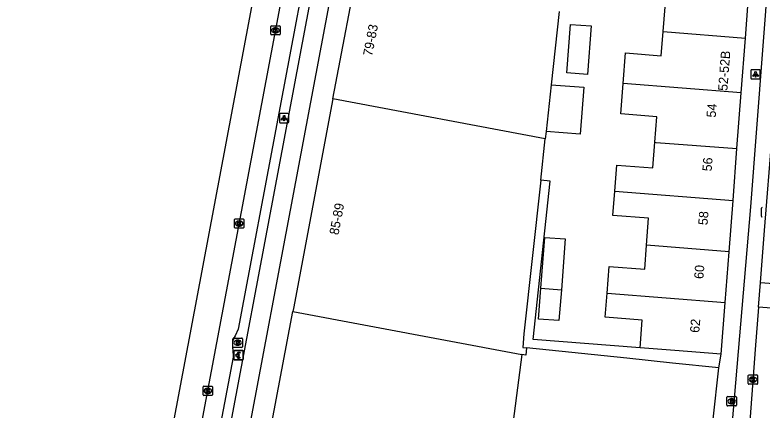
# Model space of a CAD drawing. Extents: x 161845 to 162341, y 381620 to 382158.
# Drawn here: x 161857.3 to 161937.3, y 381807.6 to 381850 of the extents above; entities that cross this region are included whole.
import ezdxf

# ---------------------------------------------------------------- set-up
doc = ezdxf.new("R2010")
doc.units = 0
for name, color, linetype in [('IMGEO_Betaalautomaat', 7, 'Continuous'), ('IMGEO_Brandkraan', 7, 'Continuous'), ('IMGEO_Fietspad_gesloten', 7, 'Continuous'), ('IMGEO_Kolk', 7, 'Continuous'), ('IMGEO_Lichtpunt', 7, 'Continuous'), ('IMGEO_OVBaan_gesloten', 7, 'Continuous'), ('IMGEO_Pand', 7, 'Continuous'), ('IMGEO_Pand_nummerreeks', 7, 'Continuous'), ('IMGEO_Parkeervlak_open', 7, 'Continuous'), ('IMGEO_Rijbaan_lokaal_gesloten', 7, 'Continuous'), ('IMGEO_Rijbaan_lokaal_open', 7, 'Continuous'), ('IMGEO_Voetpad_open', 7, 'Continuous')]:
    doc.layers.add(name, color=color, linetype=linetype)

msp = doc.modelspace()

# ---------------------------------------------------------------- linework, layer by layer
at = {"layer": 'IMGEO_Betaalautomaat'}
for p, q in [((161880.759, 381813.075), (161880.759, 381813.916)), ((161880.759, 381813.916), (161880.759, 381813.075)), ((161880.834, 381813.999), (161881.675, 381813.999)), ((161881.675, 381813.999), (161880.834, 381813.999)), ((161881.042, 381813.463), (161881.042, 381813.531)), ((161881.163, 381813.531), (161881.163, 381813.463)), ((161881.421, 381813.804), (161881.404, 381813.704)), ((161881.758, 381813.925), (161881.758, 381813.084)), ((161881.758, 381813.084), (161881.758, 381813.925)), ((161881.684, 381813), (161880.843, 381813)), ((161880.843, 381813), (161881.684, 381813)), ((161881.408, 381813.298), (161881.43, 381813.211))]:
    msp.add_line(p, q, dxfattribs=at)
for points in [[(161881.042, 381813.531), (161880.973, 381813.531), (161880.973, 381813.6), (161881.052, 381813.6)], [(161881.174, 381813.6), (161881.321, 381813.6), (161881.321, 381813.531), (161881.163, 381813.531)], [(161881.047, 381813.394), (161880.973, 381813.394), (161880.973, 381813.463), (161881.042, 381813.463)], [(161881.163, 381813.463), (161881.321, 381813.463), (161881.321, 381813.394), (161881.177, 381813.394)]]:
    msp.add_lwpolyline(points, dxfattribs=at)
for centre, radius, start, end in [((161880.837, 381813.922), 0.0779, 92.4484, 184.28452), ((161880.837, 381813.922), 0.0779, 92.4484, 184.28452), ((161881.335, 381813.524), 0.293, 73.01398, 165.01395), ((161881.341, 381813.537), 0.179, 69.32359, 159.56827), ((161881.681, 381813.922), 0.0779, 2.4484, 94.28452), ((161881.681, 381813.922), 0.0779, 2.4484, 94.28452), ((161880.837, 381813.078), 0.0779, 182.4484, 274.28452), ((161880.837, 381813.078), 0.0779, 182.4484, 274.28452), ((161881.308, 381813.449), 0.267, 191.80956, 297.03891), ((161881.341, 381813.464), 0.179, 202.76249, 291.86925), ((161881.681, 381813.078), 0.0779, 272.4484, 4.28452), ((161881.681, 381813.078), 0.0779, 272.4484, 4.28452)]:
    msp.add_arc(centre, radius, start, end, dxfattribs=at)
at = {"layer": 'IMGEO_Brandkraan'}
for p, q in [((161880.66, 381814.422), (161880.66, 381815.274)), ((161880.735, 381815.348), (161881.587, 381815.348)), ((161881.148, 381815.128), (161881.173, 381815.128)), ((161881.661, 381815.274), (161881.661, 381814.422)), ((161881.587, 381814.348), (161880.735, 381814.348)), ((161881.171, 381814.568), (161881.146, 381814.568)), ((161933.545, 381808.144), (161933.545, 381808.996)), ((161933.62, 381809.07), (161934.472, 381809.07)), ((161934.033, 381808.85), (161934.058, 381808.85)), ((161934.546, 381808.996), (161934.546, 381808.144)), ((161934.472, 381808.07), (161933.62, 381808.07)), ((161934.056, 381808.29), (161934.031, 381808.29))]:
    msp.add_line(p, q, dxfattribs=at)
for points in [[(161880.66, 381814.422), (161880.66, 381815.274)], [(161880.735, 381815.348), (161881.587, 381815.348)], [(161881.661, 381815.274), (161881.661, 381814.422)], [(161881.587, 381814.348), (161880.735, 381814.348)], [(161881.008, 381815.048), (161881.008, 381814.648), (161881.221, 381814.648)], [(161881.239, 381815.048), (161881.008, 381815.048)], [(161881.187, 381814.967), (161881.133, 381814.967), (161881.133, 381814.891)], [(161881.133, 381814.891), (161881.186, 381814.891)], [(161881.195, 381814.815), (161881.133, 381814.815), (161881.133, 381814.734)], [(161881.133, 381814.734), (161881.195, 381814.734)], [(161933.545, 381808.144), (161933.545, 381808.996)], [(161933.62, 381809.07), (161934.472, 381809.07)], [(161933.893, 381808.77), (161933.893, 381808.37), (161934.106, 381808.37)], [(161934.124, 381808.77), (161933.893, 381808.77)], [(161934.546, 381808.996), (161934.546, 381808.144)], [(161934.472, 381808.07), (161933.62, 381808.07)], [(161934.072, 381808.689), (161934.018, 381808.689), (161934.018, 381808.613)], [(161934.018, 381808.613), (161934.071, 381808.613)], [(161934.08, 381808.537), (161934.018, 381808.537), (161934.018, 381808.456)], [(161934.018, 381808.456), (161934.08, 381808.456)]]:
    msp.add_lwpolyline(points, dxfattribs=at)
for centre, radius, start, end in [((161880.737, 381815.272), 0.0765, 91.55205, 178.44795), ((161880.737, 381815.272), 0.0765, 91.55205, 178.44795), ((161881.585, 381815.272), 0.0765, 1.55205, 88.44795), ((161881.585, 381815.272), 0.0765, 1.55205, 88.44795), ((161880.737, 381814.424), 0.0765, 181.55205, 268.44795), ((161880.737, 381814.424), 0.0765, 181.55205, 268.44795), ((161881.188, 381814.929), 0.0379, 267.82845, 90.93552), ((161881.196, 381814.774), 0.0404, 269.87594, 90.50774), ((161881.227, 381814.899), 0.251, 268.66757, 293.53466), ((161881.243, 381814.903), 0.145, 59.4692, 91.53667), ((161881.268, 381814.95), 0.0922, 285.51372, 58.15012), ((161881.273, 381814.758), 0.105, 301.31148, 78.98903), ((161881.585, 381814.424), 0.0765, 271.55205, 358.44795), ((161881.585, 381814.424), 0.0765, 271.55205, 358.44795), ((161933.622, 381808.994), 0.0765, 91.55205, 178.44795), ((161933.622, 381808.994), 0.0765, 91.55205, 178.44795), ((161934.128, 381808.625), 0.145, 59.4692, 91.53667), ((161934.153, 381808.672), 0.0922, 285.51372, 58.15012), ((161934.47, 381808.994), 0.0765, 1.55205, 88.44795), ((161934.47, 381808.994), 0.0765, 1.55205, 88.44795), ((161933.622, 381808.146), 0.0765, 181.55205, 268.44795), ((161933.622, 381808.146), 0.0765, 181.55205, 268.44795), ((161934.073, 381808.651), 0.0379, 267.82845, 90.93552), ((161934.081, 381808.496), 0.0404, 269.87594, 90.50774), ((161934.112, 381808.621), 0.251, 268.66757, 293.53466), ((161934.158, 381808.48), 0.105, 301.31148, 78.98903), ((161934.47, 381808.146), 0.0765, 271.55205, 358.44795), ((161934.47, 381808.146), 0.0765, 271.55205, 358.44795)]:
    msp.add_arc(centre, radius, start, end, dxfattribs=at)
for centre, major_axis, ratio, start_param, end_param in [((161881.147, 381814.848), (-0.387, 0.002), 0.722429, 4.712389, 7.853982), ((161881.172, 381814.848), (-0.39, 0.002), 0.717154, 1.570796, 4.712389), ((161934.032, 381808.57), (-0.387, 0.002), 0.722429, 4.712389, 7.853982), ((161934.057, 381808.57), (-0.39, 0.002), 0.717154, 1.570796, 4.712389)]:
    msp.add_ellipse(centre, major_axis=major_axis, ratio=ratio, start_param=start_param, end_param=end_param, dxfattribs=at)
at = {"layer": 'IMGEO_Fietspad_gesloten'}
for points in [[(161857.316, 381682.246), (161862.987, 381712.892), (161864.774, 381722.548), (161869.854, 381750), (161870.207, 381751.91), (161895.081, 381884.229), (161897.858, 381899.101), (161916.698, 382000), (161921.558, 382026.031), (161926.346, 382051.921)], [(161907.39, 381938.834), (161899.866, 381898.705), (161897.095, 381883.929), (161872.236, 381751.615), (161871.936, 381750), (161866.402, 381720.165)]]:
    msp.add_lwpolyline(points, dxfattribs=at)
at = {"layer": 'IMGEO_Kolk'}
for p, q in [((161884.711, 381847.906), (161884.711, 381848.758)), ((161884.786, 381848.832), (161885.638, 381848.832)), ((161885.712, 381848.758), (161885.712, 381847.906)), ((161885.222, 381848.052), (161885.197, 381848.052)), ((161885.199, 381848.612), (161885.224, 381848.612)), ((161885.638, 381847.832), (161884.786, 381847.832)), ((161937.224, 381828.407), (161937.224, 381829.259)), ((161880.817, 381827.196), (161880.817, 381828.048)), ((161880.892, 381828.122), (161881.744, 381828.122)), ((161881.818, 381828.048), (161881.818, 381827.196)), ((161881.744, 381827.122), (161880.892, 381827.122)), ((161881.328, 381827.342), (161881.303, 381827.342)), ((161881.305, 381827.902), (161881.33, 381827.902)), ((161935.826, 381810.467), (161935.826, 381811.319)), ((161935.901, 381811.393), (161936.753, 381811.393)), ((161936.314, 381811.173), (161936.339, 381811.173)), ((161936.827, 381811.319), (161936.827, 381810.467)), ((161936.753, 381810.393), (161935.901, 381810.393)), ((161936.337, 381810.613), (161936.312, 381810.613)), ((161877.457, 381809.26), (161877.457, 381810.112)), ((161877.532, 381810.186), (161878.384, 381810.186)), ((161877.945, 381809.966), (161877.97, 381809.966)), ((161878.458, 381810.112), (161878.458, 381809.26)), ((161878.384, 381809.186), (161877.532, 381809.186)), ((161877.968, 381809.406), (161877.943, 381809.406))]:
    msp.add_line(p, q, dxfattribs=at)
for points in [[(161884.711, 381847.906), (161884.711, 381848.758)], [(161884.786, 381848.832), (161885.638, 381848.832)], [(161885.712, 381848.758), (161885.712, 381847.906)], [(161885.032, 381848.532), (161885.155, 381848.532), (161885.155, 381848.381), (161885.285, 381848.532), (161885.449, 381848.532), (161885.303, 381848.381), (161885.456, 381848.132), (161885.304, 381848.132), (161885.219, 381848.296), (161885.155, 381848.229), (161885.155, 381848.132), (161885.032, 381848.132), (161885.032, 381848.532)], [(161885.638, 381847.832), (161884.786, 381847.832)], [(161937.224, 381828.407), (161937.224, 381829.259)], [(161880.817, 381827.196), (161880.817, 381828.048)], [(161880.892, 381828.122), (161881.744, 381828.122)], [(161881.818, 381828.048), (161881.818, 381827.196)], [(161881.744, 381827.122), (161880.892, 381827.122)], [(161881.138, 381827.822), (161881.261, 381827.822), (161881.261, 381827.671), (161881.391, 381827.822), (161881.555, 381827.822), (161881.409, 381827.671), (161881.562, 381827.422), (161881.41, 381827.422), (161881.325, 381827.586), (161881.261, 381827.519), (161881.261, 381827.422), (161881.138, 381827.422), (161881.138, 381827.822)], [(161935.826, 381810.467), (161935.826, 381811.319)], [(161935.901, 381811.393), (161936.753, 381811.393)], [(161936.827, 381811.319), (161936.827, 381810.467)], [(161936.753, 381810.393), (161935.901, 381810.393)], [(161936.147, 381811.093), (161936.27, 381811.093), (161936.27, 381810.942), (161936.4, 381811.093), (161936.564, 381811.093), (161936.418, 381810.942), (161936.571, 381810.693), (161936.419, 381810.693), (161936.334, 381810.857), (161936.27, 381810.79), (161936.27, 381810.693), (161936.147, 381810.693), (161936.147, 381811.093)], [(161877.457, 381809.26), (161877.457, 381810.112)], [(161877.532, 381810.186), (161878.384, 381810.186)], [(161877.778, 381809.886), (161877.901, 381809.886), (161877.901, 381809.735), (161878.031, 381809.886), (161878.195, 381809.886), (161878.049, 381809.735), (161878.202, 381809.486), (161878.05, 381809.486), (161877.965, 381809.65), (161877.901, 381809.583), (161877.901, 381809.486), (161877.778, 381809.486), (161877.778, 381809.886)], [(161878.458, 381810.112), (161878.458, 381809.26)], [(161878.384, 381809.186), (161877.532, 381809.186)]]:
    msp.add_lwpolyline(points, dxfattribs=at)
for centre, start, end in [((161884.788, 381848.756), 91.55205, 178.44795), ((161884.788, 381848.756), 91.55205, 178.44795), ((161885.636, 381848.756), 1.55205, 88.44795), ((161885.636, 381848.756), 1.55205, 88.44795), ((161884.788, 381847.908), 181.55205, 268.44795), ((161884.788, 381847.908), 181.55205, 268.44795), ((161885.636, 381847.908), 271.55205, 358.44795), ((161885.636, 381847.908), 271.55205, 358.44795), ((161937.301, 381829.257), 91.55205, 178.44795), ((161937.301, 381829.257), 91.55205, 178.44795), ((161880.894, 381828.046), 91.55205, 178.44795), ((161880.894, 381828.046), 91.55205, 178.44795), ((161881.742, 381828.046), 1.55205, 88.44795), ((161881.742, 381828.046), 1.55205, 88.44795), ((161937.301, 381828.409), 181.55205, 268.44795), ((161937.301, 381828.409), 181.55205, 268.44795), ((161880.894, 381827.198), 181.55205, 268.44795), ((161880.894, 381827.198), 181.55205, 268.44795), ((161881.742, 381827.198), 271.55205, 358.44795), ((161881.742, 381827.198), 271.55205, 358.44795), ((161935.903, 381811.317), 91.55205, 178.44795), ((161935.903, 381811.317), 91.55205, 178.44795), ((161936.751, 381811.317), 1.55205, 88.44795), ((161936.751, 381811.317), 1.55205, 88.44795), ((161935.903, 381810.469), 181.55205, 268.44795), ((161935.903, 381810.469), 181.55205, 268.44795), ((161936.751, 381810.469), 271.55205, 358.44795), ((161936.751, 381810.469), 271.55205, 358.44795), ((161877.534, 381810.11), 91.55205, 178.44795), ((161877.534, 381810.11), 91.55205, 178.44795), ((161878.382, 381810.11), 1.55205, 88.44795), ((161878.382, 381810.11), 1.55205, 88.44795), ((161877.534, 381809.262), 181.55205, 268.44795), ((161877.534, 381809.262), 181.55205, 268.44795), ((161878.382, 381809.262), 271.55205, 358.44795), ((161878.382, 381809.262), 271.55205, 358.44795)]:
    msp.add_arc(centre, 0.0765, start, end, dxfattribs=at)
for centre, major_axis, ratio, start_param, end_param in [((161885.198, 381848.332), (-0.387, 0.002), 0.722429, 4.712389, 7.853982), ((161885.223, 381848.332), (-0.39, 0.002), 0.717154, 1.570796, 4.712389), ((161881.304, 381827.622), (-0.387, 0.002), 0.722429, 4.712389, 7.853982), ((161881.329, 381827.622), (-0.39, 0.002), 0.717154, 1.570796, 4.712389), ((161936.313, 381810.893), (-0.387, 0.002), 0.722429, 4.712389, 7.853982), ((161936.338, 381810.893), (-0.39, 0.002), 0.717154, 1.570796, 4.712389), ((161877.944, 381809.686), (-0.387, 0.002), 0.722429, 4.712389, 7.853982), ((161877.969, 381809.686), (-0.39, 0.002), 0.717154, 1.570796, 4.712389)]:
    msp.add_ellipse(centre, major_axis=major_axis, ratio=ratio, start_param=start_param, end_param=end_param, dxfattribs=at)
at = {"layer": 'IMGEO_Lichtpunt'}
for p, q in [((161936.11, 381844.017), (161936.11, 381843.21)), ((161936.11, 381844.017), (161936.11, 381843.21)), ((161937.012, 381844.112), (161936.204, 381844.112)), ((161937.012, 381844.112), (161936.204, 381844.112)), ((161937.106, 381843.21), (161937.106, 381844.017)), ((161937.106, 381843.21), (161937.106, 381844.017)), ((161936.204, 381843.116), (161937.012, 381843.116)), ((161936.204, 381843.116), (161937.012, 381843.116)), ((161885.625, 381839.32), (161885.625, 381838.513)), ((161885.625, 381839.32), (161885.625, 381838.513)), ((161886.527, 381839.415), (161885.719, 381839.415)), ((161886.527, 381839.415), (161885.719, 381839.415)), ((161886.621, 381838.513), (161886.621, 381839.32)), ((161886.621, 381838.513), (161886.621, 381839.32)), ((161885.719, 381838.419), (161886.527, 381838.419)), ((161885.719, 381838.419), (161886.527, 381838.419))]:
    msp.add_line(p, q, dxfattribs=at)
for points in [[(161936.484, 381843.681), (161936.523, 381843.653), (161936.335, 381843.391), (161936.297, 381843.418), (161936.484, 381843.681)], [(161936.586, 381843.633), (161936.633, 381843.633), (161936.633, 381843.311), (161936.586, 381843.311), (161936.586, 381843.633)], [(161936.696, 381843.653), (161936.734, 381843.68), (161936.921, 381843.418), (161936.882, 381843.39), (161936.696, 381843.653)], [(161885.999, 381838.984), (161886.038, 381838.956), (161885.85, 381838.694), (161885.812, 381838.721), (161885.999, 381838.984)], [(161886.101, 381838.936), (161886.148, 381838.936), (161886.148, 381838.614), (161886.101, 381838.614), (161886.101, 381838.936)], [(161886.211, 381838.956), (161886.249, 381838.983), (161886.436, 381838.721), (161886.397, 381838.693), (161886.211, 381838.956)]]:
    msp.add_lwpolyline(points, dxfattribs=at)
for centre in [(161936.609, 381843.815), (161886.124, 381839.118)]:
    msp.add_circle(centre, 0.0994, dxfattribs=at)
for centre, start, end in [((161936.204, 381844.017), 90, 180), ((161936.204, 381844.017), 90, 180), ((161937.012, 381844.017), 0, 90), ((161937.012, 381844.017), 0, 90), ((161936.204, 381843.21), 180, 270), ((161936.204, 381843.21), 180, 270), ((161937.012, 381843.21), 270, 0), ((161937.012, 381843.21), 270, 360), ((161885.719, 381839.32), 90, 180), ((161885.719, 381839.32), 90, 180), ((161886.527, 381839.32), 0, 90), ((161886.527, 381839.32), 0, 90), ((161885.719, 381838.513), 180, 270), ((161885.719, 381838.513), 180, 270), ((161886.527, 381838.513), 270, 0), ((161886.527, 381838.513), 270, 360)]:
    msp.add_arc(centre, 0.0946, start, end, dxfattribs=at)
at = {"layer": 'IMGEO_OVBaan_gesloten'}
msp.add_lwpolyline([(161858.651, 381720.96), (161859.425, 381726.158), (161861.132, 381736.231), (161869.606, 381781.344), (161897.211, 381928.16), (161915.531, 382025.949), (161915.767, 382027.092)], dxfattribs=at)
at = {"layer": 'IMGEO_Pand'}
for points in [[(161891.353, 381840.988), (161894.318, 381856.539)], [(161926.711, 381848.195), (161926.914, 381850.834), (161923.035, 381851.132), (161923.25, 381853.926)], [(161935.52, 381847.505), (161935.934, 381852.933)], [(161915.575, 381850.361), (161914.718, 381842.499)], [(161918.605, 381843.607), (161916.406, 381843.776), (161916.806, 381848.971), (161919.005, 381848.799), (161918.605, 381843.607)], [(161922.421, 381842.615), (161922.674, 381845.903), (161926.512, 381845.608), (161926.711, 381848.195)], [(161926.711, 381848.195), (161935.52, 381847.505)], [(161935.07, 381841.625), (161935.52, 381847.505)], [(161914.718, 381842.499), (161918.215, 381842.226), (161917.822, 381837.199), (161914.171, 381837.484)], [(161914.718, 381842.499), (161914.171, 381837.484)], [(161925.814, 381836.338), (161926.024, 381839.074), (161922.171, 381839.37), (161922.421, 381842.615)], [(161935.07, 381841.625), (161922.421, 381842.615)], [(161934.614, 381835.648), (161935.07, 381841.625)], [(161891.353, 381840.988), (161887.141, 381818.507), (161887.08, 381818.184)], [(161914.087, 381836.711), (161891.353, 381840.988)], [(161914.171, 381837.484), (161914.087, 381836.711)], [(161913.605, 381832.286), (161914.087, 381836.711)], [(161921.538, 381831.083), (161921.753, 381833.875), (161925.602, 381833.579), (161925.814, 381836.338)], [(161925.814, 381836.338), (161925.978, 381836.324), (161934.614, 381835.648)], [(161934.189, 381830.092), (161934.614, 381835.648)], [(161913.605, 381832.286), (161911.809, 381815.813), (161911.687, 381814.33), (161912.064, 381814.291)], [(161924.932, 381825.287), (161925.156, 381828.195), (161921.338, 381828.488), (161921.538, 381831.083)], [(161921.538, 381831.083), (161934.189, 381830.092)], [(161933.769, 381824.596), (161934.189, 381830.092)], [(161913.609, 381820.704), (161914.027, 381826.14), (161916.229, 381825.968), (161915.812, 381820.532)], [(161920.707, 381820.149), (161920.929, 381823.029), (161924.736, 381822.736), (161924.932, 381825.287)], [(161933.769, 381824.596), (161924.932, 381825.287)], [(161933.354, 381819.16), (161933.769, 381824.596)], [(161915.812, 381820.532), (161915.557, 381817.216), (161913.354, 381817.385), (161913.609, 381820.704)], [(161913.609, 381820.704), (161915.812, 381820.532)], [(161924.232, 381814.312), (161924.46, 381817.28), (161920.51, 381817.584), (161920.707, 381820.149)], [(161920.707, 381820.149), (161933.354, 381819.16)], [(161932.931, 381813.631), (161933.354, 381819.16)], [(161882.7, 381795.067), (161887.08, 381818.184)], [(161887.08, 381818.184), (161911.591, 381813.594)], [(161911.591, 381813.594), (161908.185, 381787.449)], [(161912.064, 381814.291), (161912.006, 381813.516), (161911.591, 381813.594)], [(161932.68, 381812.15), (161927.707, 381812.667), (161922.826, 381813.174), (161912.064, 381814.291)], [(161932.931, 381813.631), (161927.947, 381814.021), (161924.232, 381814.312)], [(161932.066, 381806.638), (161932.68, 381812.15)]]:
    msp.add_lwpolyline(points, dxfattribs=at)
at = {"layer": 'IMGEO_Parkeervlak_open'}
for points in [[(161894.979, 381889.343), (161893.959, 381884.074), (161881.221, 381816.302), (161880.899, 381815.584)], [(161880.65, 381814.066), (161880.687, 381813.29), (161873.981, 381777.911)]]:
    msp.add_lwpolyline(points, dxfattribs=at)
msp.add_arc((161882.501, 381814.542), 1.911, 146.95294, 194.41634, dxfattribs=at)
at = {"layer": 'IMGEO_Rijbaan_lokaal_gesloten'}
msp.add_lwpolyline([(161871.456, 381775.156), (161894.868, 381899.69), (161899.202, 381922.742)], dxfattribs=at)
at = {"layer": 'IMGEO_Rijbaan_lokaal_open'}
for points in [[(161937.134, 381821.307), (161937.573, 381826.876), (161938.367, 381837.111), (161939.211, 381848.335), (161940.276, 381862.249), (161940.498, 381864.989)], [(161936.924, 381818.645), (161937.134, 381821.307)], [(161937.134, 381821.307), (161940.353, 381821.056)], [(161936.924, 381818.645), (161936.567, 381814.112), (161935.814, 381803.997), (161934.702, 381793.974), (161934.263, 381790.508)], [(161940.145, 381818.394), (161936.924, 381818.645)]]:
    msp.add_lwpolyline(points, dxfattribs=at)
at = {"layer": 'IMGEO_Voetpad_open'}
for points in [[(161938.746, 381864.322), (161938.633, 381863.026), (161936.079, 381829.424), (161933.289, 381796.723), (161932.886, 381792.721)], [(161924.232, 381814.312), (161912.781, 381815.209), (161914.63, 381832.174), (161913.605, 381832.286)], [(161932.68, 381812.15), (161932.931, 381813.631)]]:
    msp.add_lwpolyline(points, dxfattribs=at)

# ---------------------------------------------------------------- texts
at = {"layer": 'IMGEO_Pand_nummerreeks'}
for s, rotation, p in [('79-83', 79.20569, (161895.554, 381845.511)), ('52-52B', 85.62281, (161933.579, 381841.81)), ('54', 85.62999, (161932.339, 381838.954)), ('56', 85.62999, (161931.898, 381833.187)), ('85-89', 79.38903, (161891.946, 381826.342)), ('58', 85.62999, (161931.457, 381827.422)), ('60', 85.62999, (161931.017, 381821.654)), ('62', 85.62999, (161930.576, 381815.88))]:
    msp.add_text(s, height=1, rotation=rotation, dxfattribs=at).set_placement(p)

doc.saveas('drawing.dxf')
